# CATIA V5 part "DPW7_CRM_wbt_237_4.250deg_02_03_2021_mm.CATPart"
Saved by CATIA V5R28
Part number: DPW7_CRM_wbt_237_4.250deg_02_03_2021
Bounding box of the stored display mesh (mm): x 2349.5 to 66711.891, y 0 to 29552.9, z 2310.119 to 8715.756
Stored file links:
  Z:\Scratch\04_CAD_Allgemein\Flight2Jig\Output\DPW-7\CATPart\DPW7_CRM_wbt_237_4.250deg_02_03_2021.CATPart
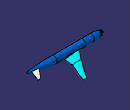
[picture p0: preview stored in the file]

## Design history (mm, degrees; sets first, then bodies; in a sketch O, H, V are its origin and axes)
Set1
  DatumSurface1 "Clean_Wing"
  DatumSurface2 "Fuselage"
  DatumSurface3 "HTP"
  DatumSurface4 "Symmetry"
  DatumSurface5 "Farfield"
Body1 (main body)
